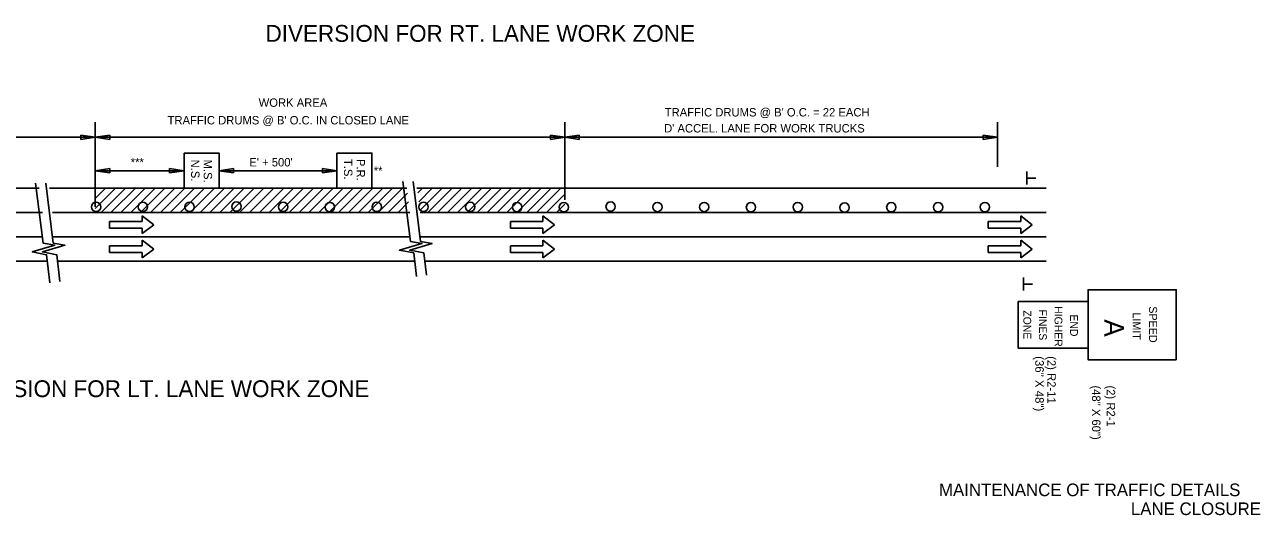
# Model space of a CAD drawing. Extents: x 1373848 to 1374003, y 380642 to 381248.
# Drawn here: x 1373915.2 to 1374003.5, y 381146.4 to 381181.4 of the extents above; entities that cross this region are included whole.
import ezdxf

# ---------------------------------------------------------------- set-up
doc = ezdxf.new("R2010")
doc.units = 0
doc.layers.add('Default', color=7, linetype='Continuous')
doc.layers.add('G-ANNO-TEXT', color=7, linetype='Continuous')

msp = doc.modelspace()

# ---------------------------------------------------------------- linework, layer by layer
at = {"layer": 'Default'}
for p, q in [((1373920.265, 381174.476), (1373920.265, 381168.441)), ((1373953.8, 381174.476), (1373953.8, 381168.941)), ((1373984.711, 381174.476), (1373984.711, 381171.285)), ((1373920.265, 381173.398), (1373889.355, 381173.398)), ((1373919.235, 381173.243), (1373919.235, 381173.552)), ((1373919.235, 381173.552), (1373920.265, 381173.398)), ((1373920.265, 381173.398), (1373919.235, 381173.243)), ((1373920.265, 381173.398), (1373921.296, 381173.552)), ((1373920.265, 381173.545), (1373920.265, 381168.441)), ((1373920.265, 381173.545), (1373920.265, 381168.441)), ((1373920.265, 381173.545), (1373920.265, 381168.441)), ((1373953.8, 381173.398), (1373920.265, 381173.398)), ((1373921.296, 381173.243), (1373920.265, 381173.398)), ((1373921.296, 381173.552), (1373921.296, 381173.243)), ((1373952.77, 381173.243), (1373952.77, 381173.552)), ((1373952.77, 381173.552), (1373953.8, 381173.398)), ((1373953.8, 381173.398), (1373952.77, 381173.243)), ((1373953.8, 381173.398), (1373954.83, 381173.552)), ((1373984.711, 381173.398), (1373953.8, 381173.398)), ((1373954.83, 381173.243), (1373953.8, 381173.398)), ((1373954.83, 381173.552), (1373954.83, 381173.243)), ((1373983.68, 381173.243), (1373983.68, 381173.552)), ((1373983.68, 381173.552), (1373984.711, 381173.398)), ((1373984.711, 381173.398), (1373983.68, 381173.243)), ((1373920.265, 381171.994), (1373920.265, 381170.418)), ((1373920.265, 381171.01), (1373921.296, 381171.165)), ((1373926.607, 381171.01), (1373920.265, 381171.01)), ((1373921.296, 381170.855), (1373920.265, 381171.01)), ((1373921.296, 381171.165), (1373921.296, 381170.855)), ((1373925.577, 381170.855), (1373925.577, 381171.165)), ((1373925.577, 381171.165), (1373926.607, 381171.01)), ((1373926.607, 381171.01), (1373925.577, 381170.855)), ((1373929.107, 381171.01), (1373930.138, 381171.165)), ((1373937.528, 381171.01), (1373929.107, 381171.01)), ((1373930.138, 381170.855), (1373929.107, 381171.01)), ((1373930.138, 381171.165), (1373930.138, 381170.855)), ((1373936.498, 381170.855), (1373936.498, 381171.165)), ((1373936.498, 381171.165), (1373937.528, 381171.01)), ((1373937.528, 381171.01), (1373936.498, 381170.855)), ((1373986.797, 381170.021), (1373986.797, 381170.948)), ((1373986.811, 381170.482), (1373987.444, 381170.482)), ((1373889.374, 381169.76), (1373916.267, 381169.76)), ((1373916.996, 381169.76), (1373920.265, 381169.76)), ((1373920.265, 381169.76), (1373942.511, 381169.76)), ((1373920.265, 381168.321), (1373921.704, 381169.76)), ((1373920.265, 381169.028), (1373920.997, 381169.76)), ((1373920.673, 381168.022), (1373922.411, 381169.76)), ((1373921.38, 381168.022), (1373923.174, 381169.816)), ((1373922.087, 381168.022), (1373923.826, 381169.76)), ((1373922.795, 381168.022), (1373924.533, 381169.76)), ((1373923.502, 381168.022), (1373925.24, 381169.76)), ((1373924.209, 381168.022), (1373925.947, 381169.76)), ((1373924.916, 381168.022), (1373926.654, 381169.76)), ((1373925.623, 381168.022), (1373927.361, 381169.76)), ((1373926.33, 381168.022), (1373928.068, 381169.76)), ((1373927.037, 381168.022), (1373928.775, 381169.76)), ((1373927.744, 381168.022), (1373929.483, 381169.76)), ((1373928.451, 381168.022), (1373930.19, 381169.76)), ((1373929.158, 381168.022), (1373930.897, 381169.76)), ((1373929.866, 381168.022), (1373931.604, 381169.76)), ((1373930.573, 381168.022), (1373932.311, 381169.76)), ((1373931.28, 381168.022), (1373933.018, 381169.76)), ((1373931.987, 381168.022), (1373933.725, 381169.76)), ((1373932.694, 381168.022), (1373934.432, 381169.76)), ((1373933.401, 381168.022), (1373935.139, 381169.76)), ((1373934.108, 381168.022), (1373935.847, 381169.76)), ((1373934.815, 381168.022), (1373936.554, 381169.76)), ((1373935.522, 381168.022), (1373937.261, 381169.76)), ((1373936.23, 381168.022), (1373937.968, 381169.76)), ((1373936.937, 381168.022), (1373938.675, 381169.76)), ((1373937.644, 381168.022), (1373939.382, 381169.76)), ((1373938.351, 381168.022), (1373940.089, 381169.76)), ((1373939.058, 381168.022), (1373940.796, 381169.76)), ((1373939.765, 381168.022), (1373941.503, 381169.76)), ((1373940.472, 381168.022), (1373942.21, 381169.76)), ((1373943.24, 381169.76), (1373953.8, 381169.76)), ((1373943.294, 381169.429), (1373943.625, 381169.76)), ((1373943.37, 381168.798), (1373944.332, 381169.76)), ((1373943.446, 381168.167), (1373945.039, 381169.76)), ((1373944.008, 381168.022), (1373945.746, 381169.76)), ((1373944.715, 381168.022), (1373946.453, 381169.76)), ((1373945.422, 381168.022), (1373947.16, 381169.76)), ((1373946.129, 381168.022), (1373947.867, 381169.76)), ((1373946.836, 381168.022), (1373948.574, 381169.76)), ((1373947.543, 381168.022), (1373949.282, 381169.76)), ((1373948.25, 381168.022), (1373949.989, 381169.76)), ((1373948.957, 381168.022), (1373950.696, 381169.76)), ((1373949.665, 381168.022), (1373951.403, 381169.76)), ((1373950.372, 381168.022), (1373952.11, 381169.76)), ((1373951.079, 381168.022), (1373952.817, 381169.76)), ((1373951.786, 381168.022), (1373953.524, 381169.76)), ((1373953.8, 381169.76), (1373988.189, 381169.76)), ((1373941.179, 381168.022), (1373942.568, 381169.41)), ((1373941.886, 381168.022), (1373942.644, 381168.779)), ((1373952.493, 381168.022), (1373953.8, 381169.329)), ((1373889.284, 381168.022), (1373916.485, 381168.022)), ((1373917.213, 381168.022), (1373920.195, 381168.022)), ((1373920.195, 381168.022), (1373942.728, 381168.022)), ((1373943.457, 381168.022), (1373953.8, 381168.022)), ((1373953.2, 381168.022), (1373953.8, 381168.622)), ((1373953.8, 381168.022), (1373988.189, 381168.022)), ((1373923.614, 381167.39), (1373921.289, 381167.39)), ((1373921.289, 381167.39), (1373921.289, 381166.915)), ((1373923.614, 381167.785), (1373923.614, 381167.39)), ((1373923.614, 381167.785), (1373924.435, 381167.153)), ((1373924.435, 381167.153), (1373923.614, 381166.52)), ((1373952.236, 381167.39), (1373949.91, 381167.39)), ((1373949.91, 381167.39), (1373949.91, 381166.915)), ((1373952.236, 381167.785), (1373952.236, 381167.39)), ((1373952.236, 381167.785), (1373953.057, 381167.153)), ((1373953.057, 381167.153), (1373952.236, 381166.52)), ((1373986.368, 381167.39), (1373984.043, 381167.39)), ((1373984.043, 381167.39), (1373984.043, 381166.915)), ((1373986.368, 381167.785), (1373986.368, 381167.39)), ((1373986.368, 381167.785), (1373987.189, 381167.153)), ((1373987.189, 381167.153), (1373986.368, 381166.52)), ((1373889.284, 381166.283), (1373916.485, 381166.283)), ((1373917.213, 381166.283), (1373920.195, 381166.283)), ((1373920.195, 381166.283), (1373942.728, 381166.283)), ((1373923.614, 381166.915), (1373921.289, 381166.915)), ((1373923.614, 381166.915), (1373923.614, 381166.52)), ((1373943.457, 381166.283), (1373953.8, 381166.283)), ((1373952.236, 381166.915), (1373949.91, 381166.915)), ((1373952.236, 381166.915), (1373952.236, 381166.52)), ((1373953.8, 381166.283), (1373988.189, 381166.283)), ((1373986.368, 381166.915), (1373984.043, 381166.915)), ((1373986.368, 381166.915), (1373986.368, 381166.52)), ((1373923.614, 381165.651), (1373921.289, 381165.651)), ((1373921.289, 381165.651), (1373921.289, 381165.177)), ((1373923.614, 381165.177), (1373921.289, 381165.177)), ((1373923.614, 381166.046), (1373923.614, 381165.651)), ((1373923.614, 381166.046), (1373924.435, 381165.414)), ((1373924.435, 381165.414), (1373923.614, 381164.782)), ((1373923.614, 381165.177), (1373923.614, 381164.782)), ((1373952.236, 381165.651), (1373949.91, 381165.651)), ((1373949.91, 381165.651), (1373949.91, 381165.177)), ((1373952.236, 381165.177), (1373949.91, 381165.177)), ((1373952.236, 381166.046), (1373952.236, 381165.651)), ((1373952.236, 381166.046), (1373953.057, 381165.414)), ((1373953.057, 381165.414), (1373952.236, 381164.782)), ((1373952.236, 381165.177), (1373952.236, 381164.782)), ((1373986.368, 381165.651), (1373984.043, 381165.651)), ((1373984.043, 381165.651), (1373984.043, 381165.177)), ((1373986.368, 381165.177), (1373984.043, 381165.177)), ((1373986.368, 381166.046), (1373986.368, 381165.651)), ((1373986.368, 381166.046), (1373987.189, 381165.414)), ((1373987.189, 381165.414), (1373986.368, 381164.782)), ((1373986.368, 381165.177), (1373986.368, 381164.782)), ((1373889.333, 381164.545), (1373916.839, 381164.545)), ((1373917.568, 381164.545), (1373920.243, 381164.545)), ((1373920.243, 381164.545), (1373943.082, 381164.545)), ((1373943.811, 381164.545), (1373953.8, 381164.545)), ((1373953.8, 381164.545), (1373988.189, 381164.545)), ((1373986.557, 381162.455), (1373986.557, 381163.383)), ((1373986.571, 381162.917), (1373987.204, 381162.917))]:
    msp.add_line(p, q, dxfattribs=at)
for points in [[(1373926.607, 381172.26), (1373929.107, 381172.26), (1373929.107, 381169.76), (1373926.607, 381169.76)], [(1373937.528, 381172.26), (1373940.028, 381172.26), (1373940.028, 381169.76), (1373937.528, 381169.76)], [(1373991.174, 381158.357), (1373986.172, 381158.357), (1373986.172, 381161.675), (1373991.174, 381161.675)], [(1373997.476, 381157.516), (1373991.174, 381157.516), (1373991.174, 381162.516), (1373997.476, 381162.516)]]:
    msp.add_lwpolyline(points, close=True, dxfattribs=at)
for points in [[(1373916.006, 381170.116), (1373916.54, 381165.84), (1373917.366, 381165.695), (1373915.763, 381165.209), (1373916.783, 381165.014), (1373917.024, 381163.007)], [(1373916.734, 381170.116), (1373917.268, 381165.84), (1373918.094, 381165.695), (1373916.491, 381165.209), (1373917.511, 381165.014), (1373917.742, 381163.094)], [(1373942.234, 381170.243), (1373942.768, 381165.968), (1373943.593, 381165.822), (1373941.991, 381165.336), (1373943.011, 381165.142), (1373943.213, 381163.457)], [(1373942.962, 381170.243), (1373943.496, 381165.968), (1373944.322, 381165.822), (1373942.719, 381165.336), (1373943.739, 381165.142), (1373943.929, 381163.561)]]:
    msp.add_lwpolyline(points, dxfattribs=at)
for centre in [(1373920.32, 381168.424), (1373923.661, 381168.424), (1373927.003, 381168.425), (1373930.344, 381168.445), (1373933.685, 381168.424), (1373937.026, 381168.413), (1373940.367, 381168.429), (1373943.708, 381168.429), (1373947.049, 381168.429), (1373950.39, 381168.413), (1373953.731, 381168.401), (1373957.072, 381168.449), (1373960.413, 381168.417), (1373963.754, 381168.417), (1373967.095, 381168.401), (1373970.436, 381168.414), (1373973.777, 381168.379), (1373977.118, 381168.401), (1373980.459, 381168.398), (1373983.8, 381168.414)]:
    msp.add_circle(centre, 0.333, dxfattribs=at)

# ---------------------------------------------------------------- texts
for s, height, p in [('DIVERSION FOR RT. LANE WORK ZONE', 1.2, (1373932.424, 381180.205)), ('WORK AREA', 0.6, (1373931.932, 381175.566)), ("TRAFFIC DRUMS @ B' O.C. IN CLOSED LANE", 0.6, (1373925.428, 381174.31)), ("TRAFFIC DRUMS @ B' O.C. = 22 EACH", 0.6, (1373960.937, 381174.877)), ("D' ACCEL. LANE FOR WORK TRUCKS", 0.6, (1373960.89, 381173.735)), ('***', 0.6, (1373922.798, 381171.313)), ("E' + 500'", 0.6, (1373931.267, 381171.313)), ('**', 0.6, (1373940.151, 381170.71)), ('DIVERSION FOR LT. LANE WORK ZONE', 1.2, (1373909.435, 381154.854))]:
    msp.add_text(s, height=height, dxfattribs=at).set_placement(p)
for s, height, p in [('N.S.', 0.6, (1373927.107, 381171.802)), ('M.S.', 0.6, (1373928.007, 381171.802)), ('T.S.', 0.6, (1373938.028, 381171.849)), ('P.R.', 0.6, (1373938.928, 381171.849)), ('ZONE', 0.5566, (1373986.552, 381161.049)), ('FINES', 0.5566, (1373987.666, 381161.099)), ('HIGHER', 0.5566, (1373988.779, 381161.345)), ('LIMIT', 0.5729, (1373994.358, 381160.893)), ('SPEED', 0.5729, (1373995.529, 381161.335)), ('END', 0.5566, (1373989.892, 381160.752)), ('A', 1.396, (1373992.336, 381160.407)), ('(36" X 48")', 0.61, (1373987.401, 381157.777)), ('(2) R2-11', 0.6, (1373988.264, 381157.777)), ('(48" X 60")', 0.6, (1373991.458, 381155.687)), ('(2) R2-1', 0.6, (1373992.505, 381155.687))]:
    msp.add_text(s, height=height, rotation=270, dxfattribs=at).set_placement(p)
at = {"layer": 'G-ANNO-TEXT'}
for s, p in [('MAINTENANCE OF TRAFFIC DETAILS', (1373980.522, 381147.788)), ('LANE CLOSURE', (1373994.227, 381146.438))]:
    msp.add_text(s, height=0.9, dxfattribs=at).set_placement(p)

doc.saveas('drawing.dxf')
